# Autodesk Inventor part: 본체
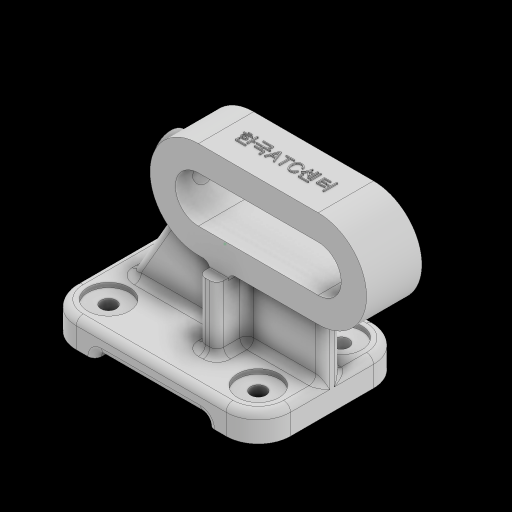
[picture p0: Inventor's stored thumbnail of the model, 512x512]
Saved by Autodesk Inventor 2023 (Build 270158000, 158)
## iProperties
Created: 2025-01
Part Number: 본체
Material: 일반
Document SubType Name: Modeling
Designer: 강의실01
Density: 1 g/cm^3
Appearance: 기본값
Mass: 134.074 g
Surface Area: 345.357 cm^2
Volume: 134.074 cm^3
Author: 강의실01
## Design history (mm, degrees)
sketch "스케치1"
  geometry: L1 (46.5, -32)-(-46.5, -32); L2 (-46.5, -32)-(-46.5, 32); L3 (-46.5, 32)-(46.5, 32); L4 (46.5, 32)-(46.5, -32); L5 (46.5, -32)-(-46.5, 32); L6 (-46.5, -32)-(46.5, 32); 1 further point
  constraints: 12 end point, 2 midpoint, 2 parallel, 1 horizontal, 1 perpendicular
  dimensions: "d0" = 93 distance of L2.end L3.end; "d1" = 64 distance of L1.end L2.end
extrude "돌출1" new body sketch "스케치1" distance "d2" = 12; taper "d3" = 0 deg
fillet "모깎기1" dims "d4" = 14
sketch "스케치2"
  geometry: L1 (-37.5, -4)-(46.5, -4); L2 (46.5, -4)-(46.5, 4); L3 (46.5, 4)-(-37.5, 4); L4 (-37.5, 4)-(-37.5, -4); L5 (0, 0)-(46.5, 0); L6 (46.5, -18)-(46.5, 18) reference; L7 (-46.5, 18)-(-46.5, -18) reference
  constraints: 10 end point, 2 parallel, 1 collinear, 1 horizontal, 1 midpoint, 1 perpendicular, 1 other
  dimensions: "d5" = 8 distance of L1.end L2.end; "d6" = 9 distance between parallel lines of L4 L7
extrude "돌출2" join sketch "스케치2" distance "d7" = 51; taper "d8" = 0 deg
sketch "스케치3"
  geometry: L1 (46.5, 18)-(46.5, 4) reference; L2 (-37.5, 4)-(46.5, 4) reference; L3 (-37.5, -4)-(-37.5, 4) reference; L4 (46.5, -4)-(-37.5, -4) reference; L5 (46.5, -4)-(46.5, -18) reference; L6 (32.5, -32)-(-32.5, -32) reference; L7 (-46.5, -18)-(-46.5, 18) reference; L8 (-32.5, 32)-(32.5, 32) reference; L9 (46.5, 4)-(46.5, -4) reference; L10 (5.5, 17)-(13.5, 17); L11 (13.5, 17)-(13.5, -17); L12 (13.5, -17)-(5.5, -17); L13 (5.5, -17)-(5.5, 17); L14 (0, 0)-(46.5, 0); A1 r 14 centre (32.5, 18) between (46.5, 18) and (32.5, 32) reference; A2 r 14 centre (32.5, -18) between (32.5, -32) and (46.5, -18) reference; A3 r 14 centre (-32.5, -18) between (-46.5, -18) and (-32.5, -32) reference; A4 r 14 centre (-32.5, 18) between (-32.5, 32) and (-46.5, 18) reference
  constraints: 10 end point, 2 parallel, 1 horizontal, 1 midpoint, 1 perpendicular, 1 other
  dimensions: "d9" = 8 distance of L10.start L10.end; "d10" = 33 distance between parallel lines of L9 L11; "d11" = 34 distance of L10.end L11.end
extrude "돌출3" join sketch "스케치3" distance "d12" = 51; taper "d13" = 0 deg
feature "면 기울기1" dims angle "d14" = 30 deg
sketch "스케치4"
  geometry: L1 (-46.5, 12)-(-37.5, 12) reference; L2 (-37.5, 12)-(-8.055, 63) reference; L3 (-8.055, 63)-(46.5, 63) reference; L4 (46.5, 63)-(46.5, 0) reference; L5 (46.5, 0)-(-46.5, 0) reference; L6 (-46.5, 0)-(-46.5, 12) reference; L7 (-24.5, 0)-(24.5, 0); L8 (24.5, 0)-(24.5, 3); L9 (24.5, 3)-(-24.5, 3); L10 (-24.5, 3)-(-24.5, 0); 3 further points
  constraints: 8 end point, 2 parallel, 1 collinear, 1 horizontal, 1 perpendicular
  dimensions: "d15" = 22 distance between parallel lines of L10 L6; "d16" = 22 distance between parallel lines of L4 L8; "d17" = 3 distance between parallel lines of L5 L9
extrude "돌출4" cut sketch "스케치4" extent not by distance; stored distance "d18" = 32; taper "d19" = 0 deg
sketch "스케치5"
  geometry: L1 (-46.5, 12)-(-37.5, 12) reference; L2 (-37.5, 12)-(-8.055, 63) reference; L3 (-8.055, 63)-(46.5, 63) reference; L4 (46.5, 63)-(46.5, 0) reference; L5 (46.5, 0)-(24.5, 0) reference; L6 (24.5, 0)-(24.5, 3) reference; L7 (24.5, 3)-(-24.5, 3) reference; L8 (-24.5, 3)-(-24.5, 0) reference; L9 (-24.5, 0)-(-46.5, 0) reference; L10 (-46.5, 0)-(-46.5, 12) reference; L11 (0.5, 63)-(52.5, 63); L12 (0.5, 84)-(52.5, 84); L13 (52.5, 42)-(0.5, 42); A1 r 21 centre (0.5, 63) between (0.5, 84) and (0.5, 42); A2 r 21 centre (52.5, 63) between (52.5, 42) and (52.5, 84); 3 further points
  constraints: 8 end point, 5 point on circle, 4 tangent, 2 centre point, 1 horizontal, 1 midpoint, 1 parallel
  dimensions: "d20" = 21 radius of A2; "d21" = 63 distance from line of L5 L11.end; "d22" = 120 distance from line of point (73.5, 63) L10; "d23" = 52 distance of L11.end L11.start
extrude "돌출5" join sketch "스케치5" stored distance "d24" = 24; taper "d25" = 0 deg
node "작업 평면1"
sketch "스케치6"
  geometry: 1 further point
sketch "스케치7"
  geometry: L1 (5, 16)-(5, 29) reference; L2 (5, 29)-(13, 29) reference; L3 (13, 29)-(13, 16) reference; L4 (13, 16)-(46, 16) reference; L5 (46, 16)-(46, 8) reference; L6 (46, 8)-(13, 8) reference; L7 (13, 8)-(13, -5) reference; L8 (13, -5)-(5, -5) reference; L9 (5, -5)-(5, 8) reference; L10 (5, 8)-(-21.834, 8) reference; L11 (-21.834, 8)-(-21.834, 16) reference; L12 (-21.834, 16)-(5, 16) reference; L13 (5, 29)-(13, 29) reference; L14 (13, 29)-(13, 16) reference; L15 (5, 29)-(13, 29); L16 (13, 29)-(13, 24); L17 (13, 24)-(5, 24); L18 (5, 24)-(5, 29); L19 (13, 8)-(13, -5) reference; L20 (5, -5)-(13, -5); L21 (13, -5)-(13, 0); L22 (13, 0)-(5, 0); L23 (5, 0)-(5, -5); 5 further points
  constraints: 16 end point, 4 parallel, 2 horizontal, 2 perpendicular, 2 point on line
  dimensions: "d27" = 5 distance between parallel lines of L17 L2; "d28" = 5 distance between parallel lines of L8 L22
extrude "돌출6" cut sketch "스케치7" extent not by distance; stored distance "d29" = 0; taper "d30" = 0 deg
sketch "스케치8"
  geometry: L1 (-46.5, 12)-(-37.5, 12) reference; L2 (-37.5, 12)-(-15.741, 49.687) reference; L3 (0.5, 84)-(52.5, 84) reference; L4 (52.5, 42)-(46.5, 42) reference; L5 (46.5, 42)-(46.5, 0) reference; L6 (46.5, 0)-(24.5, 0) reference; L7 (24.5, 0)-(24.5, 3) reference; L8 (24.5, 3)-(-24.5, 3) reference; L9 (-24.5, 3)-(-24.5, 0) reference; L10 (-24.5, 0)-(-46.5, 0) reference; L11 (-46.5, 0)-(-46.5, 12) reference; L12 (0.5, 63)-(52.5, 63); L13 (0.5, 73)-(52.5, 73); L14 (52.5, 53)-(0.5, 53); A1 r 21 centre (0.5, 63) between (0.5, 84) and (-15.741, 49.687) reference; A2 r 21 centre (52.5, 63) between (52.5, 42) and (52.5, 84) reference; A3 r 21 centre (0.5, 63) between (0.5, 84) and (0.5, 42) reference; A4 r 10 centre (0.5, 63) between (0.5, 73) and (0.5, 53); A5 r 10 centre (52.5, 63) between (52.5, 53) and (52.5, 73); 2 further points
  constraints: 8 end point, 4 point on circle, 4 tangent, 2 centre point, 1 horizontal, 1 midpoint, 1 parallel
  dimensions: "d31" = 10 radius of A5
extrude "돌출7" cut sketch "스케치8" extent not by distance; stored distance "d32" = 0; taper "d33" = 0 deg
sketch "스케치9"
  geometry: A1 r 14 centre (-32.5, 18) between (-32.5, 32) and (-46.5, 18) reference; A2 r 14 centre (32.5, 18) between (46.5, 18) and (32.5, 32) reference; A3 r 14 centre (-32.5, -18) between (-46.5, -18) and (-32.5, -32) reference; A4 r 14 centre (32.5, -18) between (32.5, -32) and (46.5, -18) reference; 5 further points
  constraints: 4 coincident
hole "구멍1" sketch "스케치9" at (-32.5, -18), (32.5, -18), (-32.5, 18), (32.5, 18) diameter "d34" = 6.6; stored, may be unused: countersink angle "d38" = 90 deg, drill point angle "d40" = 118 deg; dims "d35" = 8, "d36" = 18, "d37" = 2, "d39" = 10
node "작업 평면3"
  node "작업 평면2"
sketch "스케치10"
  geometry: L1 (-53, -18)-(-53, 18) reference; L2 (31, -12)-(31, 12) reference; C1 r 8 at (10, 0); 2 further points
  constraints: 1 centre point, 1 horizontal alignment, 1 midpoint
  dimensions: "d42" = 16 diameter of C1; "d43" = 63 distance from line of L1 C1.centre
extrude "돌출8" join sketch "스케치10" stored distance "d44" = 10; taper "d45" = 0 deg
sketch "스케치11"
  geometry: C1 r 4.5 at (0, 0); 1 further point
  constraints: 1 centre point
  dimensions: "d46" = 9 diameter of C1
extrude "돌출9" cut sketch "스케치11" stored distance "d47" = 10; taper "d48" = 0 deg
fillet "모깎기2" dims "d49" = 3
fillet "모깎기3" dims "d50" = 3
fillet "모깎기4" dims "d51" = 3
fillet "모깎기5" dims "d52" = 3
fillet "모깎기6" dims "d53" = 3
fillet "모깎기7" dims "d54" = 3
fillet "모깎기8" dims "d55" = 3
sketch "스케치12"
  geometry: L1 (52, 24)-(52, 0) reference; 2 further points
  constraints: 1 horizontal alignment, 1 other
  dimensions: "d56" = 26 distance from line of L1 point (26, 12)
feature "엠보싱1" sketch "스케치12" dims "d0" = 93, "d1" = 64, "d5" = 8, "d6" = 9, "d57" = 0.5, "d58" = 0
node "솔리드1"
node "절단 모서리 투영1"
node "절단 모서리 투영2"
node "절단 모서리 투영3"
node "절단 모서리 투영4"
node "절단 모서리 투영5"
feature "A9D066F2-1C7D-4E18-AEED-F7BC21143FA4" dims "d34" = 6.6, "d35" = 8, "d36" = 18, "d37" = 2, "d38" = 90 deg, "d39" = 10, "d40" = 118 deg
other parameters: "d26" = -44, "d41" = -24
